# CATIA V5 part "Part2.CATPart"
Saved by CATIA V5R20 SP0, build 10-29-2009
Part number: Part2
Bounding box of the stored display mesh (mm): x -2100 to 2100, y -4000 to 4440, z 0 to 1400
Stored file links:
  E:\新建文件夹 (2)\Part2.CATPart
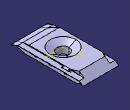
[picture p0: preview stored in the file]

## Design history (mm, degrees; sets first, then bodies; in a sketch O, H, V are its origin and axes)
Body1 (main body)
  Sketch1 on xy-plane, origin (0, 0, 0), H (1, 0, 0), V (0, 1, 0)
    line L1 (1500, 2200) -> (1500, -2200)
    line L2 (1500, -2200) -> (-1500, -2200)
    line L3 (-1500, -2200) -> (-1500, 2200)
    line L4 (-1500, 2200) -> (1500, 2200)
    length L1 = 4400
    length L2 = 3000
    vertical: L1 V, L3 V
    horizontal: L2 H, L4 H
    equidistance: L1 L3 O, L2 L4 O
  Pad1: profile Sketch1, direction (0, 0, 1), length 1400
  Sketch2 on face of Pad3, origin (-1500, 0, 0), H (0, -1, 0), V (0, 0, 1)
    circle A1 centre (-100, 300) radius 50
    circle A2 centre (100, 300) radius 50
    circle A3 centre (1700, 300) radius 50
    circle A4 centre (1900, 300) radius 50
    circle A5 centre (-1700, 300) radius 50
    circle A6 centre (-1900, 300) radius 50
    circle A7 centre (3300, 450) radius 50
    circle A8 centre (-3850, 500) radius 50
  Sketch3 on face of Pad1 from Sketch1.L1, origin (1500, 0, 0), H (0, 1, 0), V (0, 0, 1)
    line L1 (-2200, 1400) -> (-2200, 0)
    point P1 (-2200, 0)
    line L2 (-2200, 1400) -> (-4000, 700)
    line L3 (-4000, 700) -> (-4000, 300)
    line L4 (-4000, 300) -> (-3120, 0)
    point P5 (-3120, 0)
    line L5 (-3120, 0) -> (-2200, 0)
    coincidence: P1 H, P5 H
    vertical: L1 V, L3 V
    horizontal: L5 H
  Pad2: profile Sketch3, direction (-1, 0, 0), length 3000
  Sketch4 on face of Pad2, origin (-1500, 0, 0), H (0, -1, 0), V (0, 0, 1)
    line L1 (-2200, 1400) -> (-2200, 0)
    point P1 (-2200, 0)
    point P2 (-2200, 1400)
    reference projected line E1 (-2200, 0) -> (-2200, 1400) from edge [face of Pad2 | face of Pad1 from Sketch1.L4]
    line L2 (-2200, 1400) -> (-3385, 1400)
    point P3 (-2200, 1400)
    line L3 (-3385, 1400) -> (-4440, 690)
    point P5 (-4440, 690)
    line L4 (-4440, 690) -> (-3125, 0)
    point P6 (-4440, 690)
    point P7 (-3125, 0)
    line L5 (-2200, 0) -> (-3125, 0)
    point P8 (-3125, 0)
    reference projected line E2 (-2200, 1400) -> (2200, 1400) from edge [face of Pad2 | end face of Pad1]
    reference projected line E3 (-2200, 1400) -> (2200, 1400) from edge [face of Pad2 | end face of Pad1]
    reference projected line E4 (-2200, 0) -> (2200, 0) from edge [face of Pad2 | face of Pad2]
    coincidence: P1 H, L1 E1, P6 P5, P3 P2, P7 P8, E3 L2, E4 L5
    vertical: L1 V
    horizontal: L2 H
    parallelism: L2 L5, E2 L2
  Pad3: profile Sketch4, direction (1, 0, 0), length 3000
  Sketch5 on face of Pad3, origin (-1500, 0, 0), H (0, -1, 0), V (0, 0, 1)
    line L1 (-3979.3662, 1000) -> (3228.5714, 1000)
    line L2 (-3979.3662, 1000) -> (-4440, 690)
    reference projected line E1 (-3385, 1400) -> (-4440, 690) from edge [face of Pad3 from Sketch4.L3 | face of Pad3]
    point P3 (-4440, 690)
    line L3 (3228.5714, 1000) -> (4000, 700)
    point P4 (4000, 700)
    reference projected point E2 (4000, 700) from vertex [face of Pad2 from Sketch3.L3 | end face of Pad2 | face of Pad2 from Sketch3.L2]
    line L4 (-3967.1599, 960) -> (3221.0674, 960)
    line L5 (-3967.1599, 960) -> (-4399.744, 668.8771)
    line L6 (-4440, 690) -> (-4399.744, 668.8771)
    point P5 (-4440, 690)
    line L7 (3221.0674, 960) -> (4000, 657.0818)
    line L8 (4000, 700) -> (4000, 657.0818)
    horizontal: L1 H, L4 H
    parallelism: L2 E1
    coincidence: P4 E2, P5 L2, P3 P5
    vertical: L8 V
  Pad4: profile Sketch5, direction (-1, 0, 0), length 600
  Sketch6 on face of Pad3, origin (1500, 0, 0), H (0, 1, 0), V (0, 0, 1)
    line L1 (-3228.5714, 1000) -> (3979.3662, 1000)
    line L2 (-3221.0674, 960) -> (3967.1599, 960)
    line L3 (3979.3662, 1000) -> (4440, 690)
    reference projected line E1 (3385, 1400) -> (4440, 690) from edge [face of Pad3 | face of Pad4]
    line L4 (3967.1599, 960) -> (4399.744, 668.8771)
    line L5 (4440, 690) -> (4399.744, 668.8771)
    line L6 (-3228.5714, 1000) -> (-4000, 700)
    reference projected line E2 (-2200, 1400) -> (-4000, 700) from edge [face of Pad4 | face of Pad3]
    line L7 (-3221.0674, 960) -> (-4000, 657.0818)
    line L8 (-4000, 700) -> (-4000, 657.0818)
    reference projected line E3 (-4000, 700) -> (-4000, 300) from edge [face of Pad4 | face of Pad3]
    horizontal: L1 H, L2 H
    coincidence: L3 E1, L6 E2, L8 E3
    vertical: L8 V
  Pad5: profile Sketch6, direction (1, 0, 0), length 600
  Sketch7 on zx-plane, origin (0, 0, 0), H (-1, 0, 0), V (0, 0, 1)
    point P2 (-1800, 1400)
    line L1 (-1800, 1400) -> (-1500, 1000)
    line L2 (1800, 1400) -> (1500, 1000)
    line L3 (-1800, 1400) -> (-1500, 1400)
    point P5 (-1800, 1400)
    line L4 (-1500, 1400) -> (-1500, 1000)
    line L5 (1800, 1400) -> (1500, 1400)
    line L6 (1500, 1400) -> (1500, 1000)
    horizontal: L3 H, L5 H
    vertical: L4 V, L6 V
    coincidence: P2 P5
  Pad6: profile Sketch7, direction (0, 1, 0), length 3385, opposite side length 3228.57
  Sketch8 on face of Pad6, origin (0, 0, 1400), H (1, 0, 0), V (0, 1, 0)
    point P1 (0, 3979.37)
  Body2
    Plane1: type Offset, RefPlane xy-plane, Offset 1400
    Sketch9 on Plane1, origin (0, 0, 1400), H (1, 0, 0), V (0, 1, 0)
      line L1 (1500, 3385) -> (1800, 3385)
      line L2 (1800, 3385) -> (1800, 2785)
      line L3 (1800, 2785) -> (1500, 3385)
      line L4 (-1500, 3385) -> (-1800, 3385)
      line L5 (-1800, 3385) -> (-1800, 2785)
      line L6 (-1800, 2785) -> (-1500, 3385)
      horizontal: L1 H, L4 H
      vertical: L2 V, L5 V
    Pad7: profile Sketch9, direction (0, 0, -1), length 400
  Remove1: tool Body2
  Body3
    Sketch10 on yz-plane, origin (0, 0, 0), H (0, 1, 0), V (0, 0, 1)
      line L1 (-2200, 1400) -> (-3228.57, 1400)
      line L2 (-3228.57, 1400) -> (-3228.57, 1000)
      line L3 (-3228.57, 1000) -> (-2200, 1400)
      horizontal: L1 H
      vertical: L2 V
    Pad8: profile Sketch10, direction (1, 0, 0), length 2000, mirrored extent
  Remove2: tool Body3
  Sketch11 on face of Pad3, origin (1500, 0, 0), H (0, 1, 0), V (0, 0, 1)
    point P1 (2700, 300)
    point P3 (-3400, 300)
    circle A1 centre (100, 300) radius 50
    circle A2 centre (-100, 300) radius 50
    circle A3 centre (-1900, 300) radius 50
    circle A4 centre (1700, 300) radius 50
    circle A5 centre (1900, 300) radius 50
    circle A6 centre (-3300, 450) radius 50
    circle A7 centre (3850, 500) radius 50
    circle A8 centre (-1700, 300) radius 50
    point P11 (-1750, 300)
    radius A2 = 50
    coincidence: A8 P11
  Body4
    Pad9: profile Sketch11, direction (1, 0, 0), length 100, mirrored extent
  Remove3: tool Body4
  Body5
    Pad10: profile Sketch2, direction (-1, 0, 0), length 100, mirrored extent
  Remove4: tool Body5
  Body6
    Plane2: type Offset, RefPlane xy-plane, Offset 1400
    Plane3: type Offset, RefPlane xy-plane, Offset 1000
    Sketch12 on Plane3, origin (0, 0, 1000), H (1, 0, 0), V (0, 1, 0)
      point P1 (160, 0)
      circle A1 centre (0, 0) radius 700
      point P2 (0, 0)
      point P3 (0, 200)
      coincidence: P1 H, P2 V, P3 V
    Sketch13 on Plane2, origin (0, 0, 1400), H (1, 0, 0), V (0, 1, 0)
      circle A1 centre (0, 0) radius 1500
      point P1 (0, 0)
      coincidence: P1 V
    Loft1: solid, Sections (Sketch12; Sketch13)
  Remove5: tool Body6
  Body7
    Plane4: type Offset, RefPlane xy-plane, Offset 1000
    Sketch14 on Plane4, origin (0, 0, 1000), H (1, 0, 0), V (0, 1, 0)
      circle A1 centre (0, 0) radius 700
      point P1 (0, 700)
      coincidence: A1 P1, P1 V
    Pad11: profile Sketch14, direction (0, 0, -1), length 800
  Remove6: tool Body7
  Sketch15 on face of Pad3, origin (1500, 0, 0), H (0, 1, 0), V (0, 0, 1)
    circle A1 centre (1700, 1100) radius 50
  Pad12: profile Sketch15, direction (1, 0, 0), length 350, mirrored extent
  Sketch16 on zx-plane, origin (0, 0, 0), H (-1, 0, 0), V (0, 0, 1)
    circle A1 centre (-1800, 1100) radius 50
  Pad13: profile Sketch16, direction (0, 1, 0), length 1900, opposite side length -1650
  Sketch17 on end face of Pad13, origin (0, 1900, 0), H (-1, 0, 0), V (0, 0, 1)
    circle A1 centre (-1800.0811, 1180) radius 130
  Pad14: profile Sketch17, direction (0, 1, 0), length 600
  Sketch18 on end face of Pad14, origin (0, 2500, 0), H (-1, 0, 0), V (0, 0, 1)
    circle A1 centre (-1800, 1100) radius 30
  Pad15: profile Sketch18, direction (0, 1, 0), length 200
  Sketch19 on face of Pad3, origin (-1500, 0, 0), H (0, -1, 0), V (0, 0, 1)
    circle A1 centre (0, 500) radius 50
    point P1 (0, 500)
    point P2 (0, 550)
    circle A2 centre (-1800, 500) radius 50
    circle A3 centre (1800, 500) radius 50
    coincidence: P1 V, A1 P2, P2 V
  Pad16: profile Sketch19, direction (-1, 0, 0), length 100
  Sketch20 on face of Pad3, origin (1500, 0, 0), H (0, 1, 0), V (0, 0, 1)
    circle A1 centre (0, 500) radius 50
    point P1 (0, 500)
    point P2 (0, 550)
    circle A2 centre (1800, 500) radius 50
    circle A3 centre (-1800, 500) radius 50
    coincidence: P1 V, A1 P2, P2 V
  Pad17: profile Sketch20, direction (1, 0, 0), length 100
